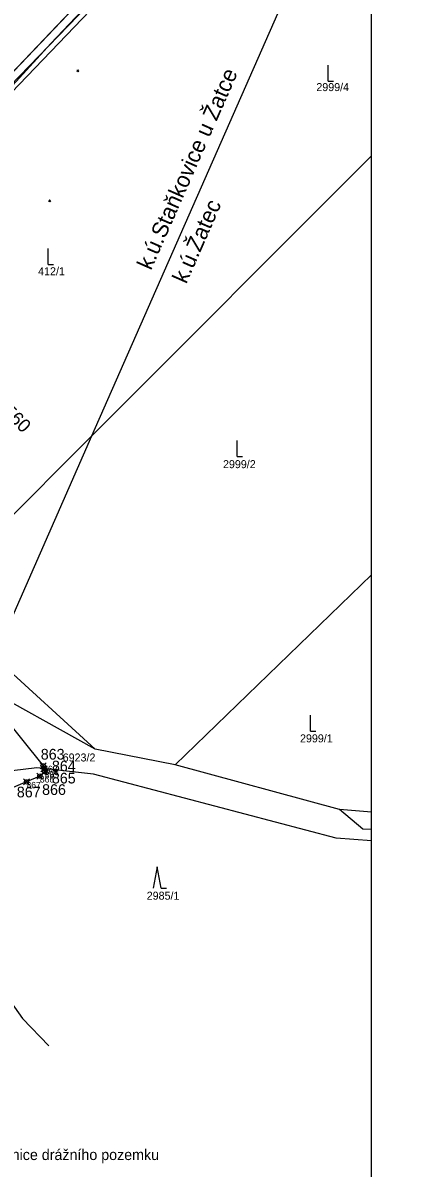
# Model space of a CAD drawing. Extents: x -800194 to -799078, y -1007177 to -1006597.
# Drawn here: x -799377.8 to -799302.5, y -1007068 to -1006853.3 of the extents above; entities that cross this region are included whole.
import ezdxf

# ---------------------------------------------------------------- set-up
doc = ezdxf.new("R2010")
doc.units = 0
for name, color, linetype in [('Dočasné zábory', 7, 'Continuous'), ('Legenda', 7, 'Continuous'), ('Legenda 1', 7, 'Continuous'), ('Vrstva 18', 7, 'Continuous'), ('Vrstva 49', 7, 'Continuous'), ('Vrstva 53', 7, 'Continuous'), ('Vrstva 55', 7, 'Continuous'), ('Vrstva 57', 7, 'Continuous'), ('Vrstva 58', 7, 'Continuous'), ('Vrstva 60', 7, 'Continuous')]:
    doc.layers.add(name, color=color, linetype=linetype)

msp = doc.modelspace()

# ---------------------------------------------------------------- linework, layer by layer
at = {"layer": 'Dočasné zábory'}
for p, q in [((-799374.53, -1006993.11), (-799373.4, -1006991.98)), ((-799374.53, -1006991.98), (-799373.4, -1006993.11)), ((-799374.38, -1006993.68), (-799373.24, -1006992.55)), ((-799374.38, -1006992.55), (-799373.24, -1006993.68)), ((-799374.23, -1006994.23), (-799373.09, -1006993.1)), ((-799374.23, -1006993.1), (-799373.09, -1006994.23)), ((-799377.66, -1006996.14), (-799376.53, -1006995.01)), ((-799377.66, -1006995.01), (-799376.53, -1006996.14)), ((-799375.15, -1006995.06), (-799374.02, -1006993.92)), ((-799375.15, -1006993.92), (-799374.02, -1006995.06))]:
    msp.add_line(p, q, dxfattribs=at)
msp.add_lwpolyline([(-799409.79, -1006894.08), (-799409.48, -1006895.36), (-799407.32, -1006903.81), (-799399.52, -1006945.6), (-799393.3, -1006959.22), (-799387.62, -1006968.78), (-799386.5, -1006977.04), (-799373.97, -1006992.55), (-799373.81, -1006993.12), (-799373.66, -1006993.66), (-799374.58, -1006994.49), (-799377.09, -1006995.58), (-799395.45, -1007003.29), (-799408.65, -1007008.83)], dxfattribs=at)
for centre in [(-799373.97, -1006992.55), (-799373.81, -1006993.12), (-799377.09, -1006995.58), (-799374.58, -1006994.49), (-799373.66, -1006993.66)]:
    msp.add_circle(centre, 0.4, dxfattribs=at)
at = {"layer": 'Legenda 1'}
msp.add_lwpolyline([(-800193.4, -1007176.65), (-799312.4, -1007176.65), (-799312.4, -1006766.65), (-800193.4, -1006766.65)], close=True, dxfattribs=at)
at = {"layer": 'Vrstva 49'}
for p, q in [((-799367.64, -1006862.11), (-799367.29, -1006862.46)), ((-799367.64, -1006862.46), (-799367.29, -1006862.11)), ((-799372.92, -1006886.5), (-799372.57, -1006886.86)), ((-799372.92, -1006886.86), (-799372.57, -1006886.5))]:
    msp.add_line(p, q, dxfattribs=at)
msp.add_lwpolyline([(-799405.31, -1006888.8), (-799396.79, -1006882.07), (-799386.95, -1006872.93), (-799372.54, -1006857.15), (-799356.35, -1006840.04), (-799339.51, -1006822.21), (-799317.89, -1006801.14), (-799302.5, -1006781.46)], dxfattribs=at)
at = {"layer": 'Vrstva 53'}
msp.add_lwpolyline([(-799312.4, -1006791.98), (-799331.37, -1006811.87), (-799413.75, -1006898.23), (-799418.41, -1006902.53), (-799423.07, -1006906.83), (-799433.4, -1006916.39), (-799469.5, -1006946.86), (-799487.22, -1006958.47), (-799495.25, -1006963.74), (-799521.98, -1006977.8), (-799546.71, -1006987.83)], dxfattribs=at)
at = {"layer": 'Vrstva 55'}
for p, q in [((-799413.75, -1006898.23), (-799331.37, -1006811.87)), ((-799364.81, -1006930.69), (-799312.4, -1006878.2)), ((-799393.3, -1006959.22), (-799364.81, -1006930.69)), ((-799383.1, -1006972.22), (-799364.81, -1006930.69)), ((-799312.4, -1006956.76), (-799349.19, -1006992.39)), ((-799364.19, -1006989.42), (-799383.1, -1006972.22)), ((-799349.19, -1006992.39), (-799364.19, -1006989.42)), ((-799318.36, -1007000.74), (-799349.19, -1006992.39)), ((-799312.4, -1007001.25), (-799318.36, -1007000.74))]:
    msp.add_line(p, q, dxfattribs=at)
for points in [[(-799329.14, -1006812.3), (-799409.48, -1006895.36), (-799407.32, -1006903.81)], [(-799328.26, -1006812.47), (-799403.59, -1006891), (-799407.32, -1006903.81)], [(-799364.81, -1006930.69), (-799327.63, -1006846.25), (-799317.77, -1006827.17)], [(-799364.19, -1006989.42), (-799386.5, -1006977.04), (-799383.1, -1006972.22)], [(-799312.4, -1007006.62), (-799318.99, -1007006.15), (-799364.52, -1006994.13), (-799375.17, -1006992.97), (-799396.86, -1006995.59)], [(-799396.86, -1006995.59), (-799394.17, -1007010.32), (-799387.01, -1007026.98), (-799377.82, -1007039.94), (-799372.89, -1007045.05)], [(-799312.4, -1007004.53), (-799313.97, -1007004.43), (-799318.36, -1007000.74)]]:
    msp.add_lwpolyline(points, dxfattribs=at)
at = {"layer": 'Vrstva 58'}
for p, q in [((-799320.53, -1006864.22), (-799320.53, -1006861.22)), ((-799320.53, -1006864.22), (-799319.53, -1006864.22)), ((-799373.05, -1006898.58), (-799373.05, -1006895.58)), ((-799373.05, -1006898.58), (-799372.05, -1006898.58)), ((-799337.58, -1006934.56), (-799337.58, -1006931.56)), ((-799337.58, -1006934.56), (-799336.58, -1006934.56)), ((-799323.8, -1006986.09), (-799323.8, -1006983.09)), ((-799323.8, -1006986.09), (-799322.8, -1006986.09)), ((-799352.59, -1007011.5), (-799353.34, -1007015.5)), ((-799351.84, -1007015.5), (-799352.59, -1007011.5)), ((-799351.84, -1007015.5), (-799350.84, -1007015.5))]:
    msp.add_line(p, q, dxfattribs=at)
at = {"layer": 'Vrstva 60'}
for p, q in [((-799373.96, -1006992.55), (-799373.96, -1006992.55)), ((-799373.81, -1006993.12), (-799373.81, -1006993.12)), ((-799374.58, -1006994.49), (-799374.58, -1006994.49)), ((-799373.66, -1006993.66), (-799373.66, -1006993.66)), ((-799377.09, -1006995.58), (-799377.09, -1006995.58))]:
    msp.add_line(p, q, dxfattribs=at)

# ---------------------------------------------------------------- texts
at = {"layer": 'Dočasné zábory'}
for s, p in [('863', (-799374.41, -1006991.39)), ('864', (-799372.32, -1006993.6)), ('865', (-799372.33, -1006995.87)), ('867', (-799378.9, -1006998.48)), ('866', (-799374.16, -1006998.02))]:
    msp.add_text(s, height=2, rotation=360, dxfattribs=at).set_placement(p)
at = {"layer": 'Legenda'}
msp.add_text('Hranice drážního pozemku', height=2, rotation=360, dxfattribs=at).set_placement((-799384.18, -1007066.46))
at = {"layer": 'Vrstva 18'}
msp.add_text('evid. km 204,560', height=2.5, rotation=315.0595, dxfattribs=at).set_placement((-799395.8, -1006912.33))
at = {"layer": 'Vrstva 55'}
for s, p in [('k.ú.Staňkovice u Žatce', (-799353.73, -1006899.81)), ('k.ú.Žatec', (-799347.12, -1006902.36))]:
    msp.add_text(s, height=3, rotation=66.2843, dxfattribs=at).set_placement(p)
at = {"layer": 'Vrstva 57'}
for s, p in [('2999/4', (-799322.72, -1006866.09)), ('412/1', (-799374.91, -1006900.61)), ('2999/2', (-799340.23, -1006936.77)), ('2999/1', (-799325.78, -1006988.17)), ('6923/2', (-799370.3, -1006991.75)), ('2985/1', (-799354.54, -1007017.66))]:
    msp.add_text(s, height=1.5, dxfattribs=at).set_placement(p)
at = {"layer": 'Vrstva 60'}
for s, p in [('863', (-799373.96, -1006993.75)), ('864', (-799373.81, -1006994.32)), ('866', (-799374.58, -1006995.69)), ('865', (-799373.66, -1006994.86)), ('867', (-799377.09, -1006996.78))]:
    msp.add_text(s, height=1.2, dxfattribs=at).set_placement(p)

doc.saveas('drawing.dxf')
